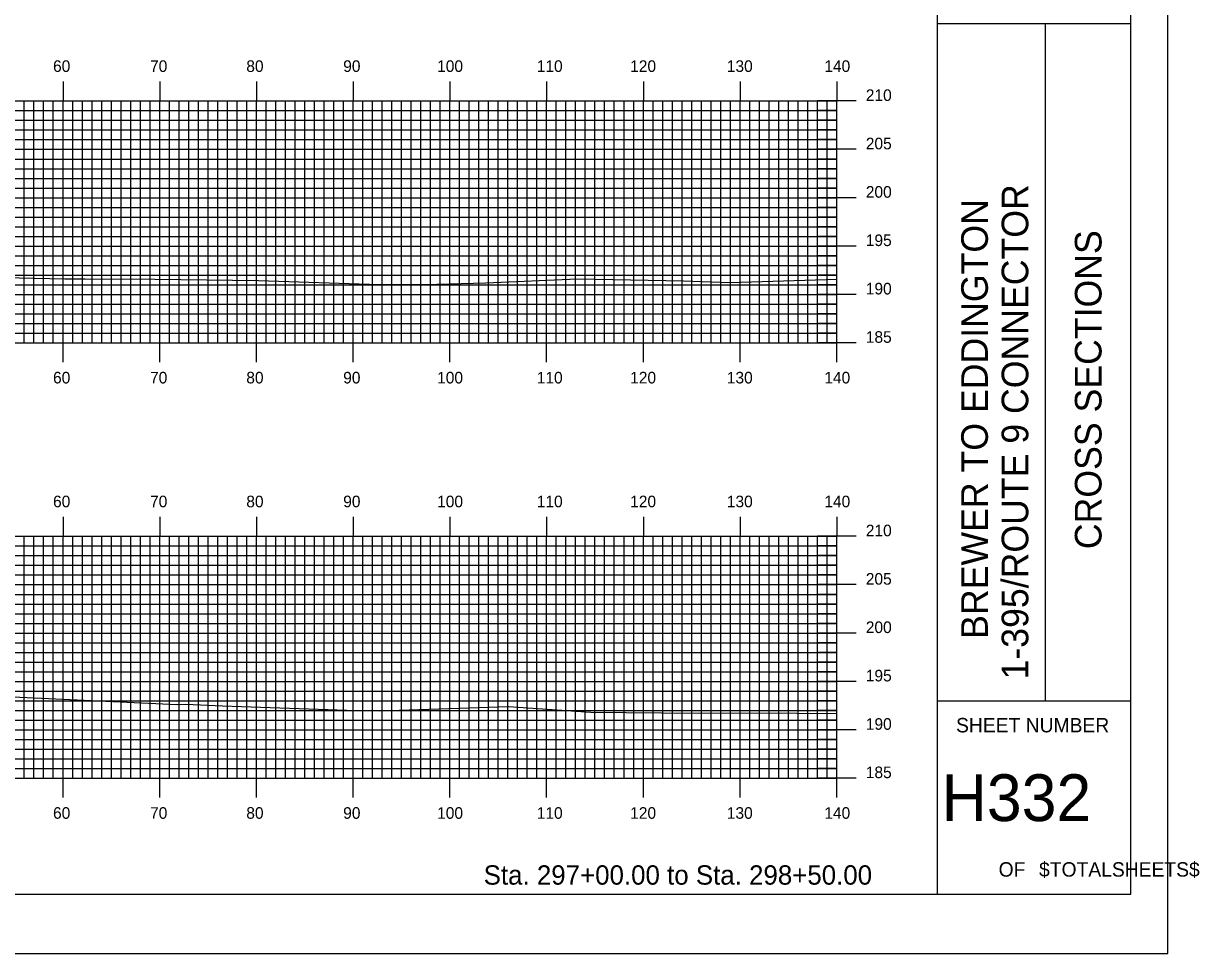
# Model space of a CAD drawing. Extents: x 1814915 to 1815259, y 442591 to 442811.
# Drawn here: x 1815136.9 to 1815258.5, y 442590.5 to 442686.7 of the extents above; entities that cross this region are included whole.
import ezdxf

# ---------------------------------------------------------------- set-up
doc = ezdxf.new("R2010")
doc.units = 0
for name, color, linetype in [('BORDER', 7, 'Continuous'), ('H_V ANNOTATION', 7, 'Continuous'), ('MAJOR', 7, 'Continuous'), ('MINOR', 7, 'Continuous'), ('PLOT BOUNDARY', 7, 'Continuous'), ('S_Roadway_Centerline', 7, 'Continuous')]:
    doc.layers.add(name, color=color, linetype=linetype)

msp = doc.modelspace()

# ---------------------------------------------------------------- linework, layer by layer
at = {"layer": 'BORDER'}
for p, q in [((1815231.42, 442596.67), (1815231.42, 442806.67)), ((1815231.42, 442686.67), (1815251.42, 442686.67)), ((1815242.6, 442616.67), (1815242.6, 442686.67)), ((1815231.42, 442616.67), (1815251.42, 442616.67))]:
    msp.add_line(p, q, dxfattribs=at)
msp.add_lwpolyline([(1814931.42, 442596.67), (1815251.42, 442596.67), (1815251.42, 442806.67), (1814931.42, 442806.67)], close=True, dxfattribs=at)
at = {"layer": 'MAJOR'}
for p, q in [((1815141.02, 442680.67), (1815141.02, 442678.67)), ((1815151.02, 442680.67), (1815151.02, 442678.67)), ((1815161.02, 442680.67), (1815161.02, 442678.67)), ((1815171.02, 442680.67), (1815171.02, 442678.67)), ((1815181.02, 442680.67), (1815181.02, 442678.67)), ((1815191.02, 442680.67), (1815191.02, 442678.67)), ((1815201.02, 442680.67), (1815201.02, 442678.67)), ((1815211.02, 442680.67), (1815211.02, 442678.67)), ((1815221.02, 442680.67), (1815221.02, 442678.67)), ((1814941.02, 442678.67), (1815221.02, 442678.67)), ((1814941.02, 442678.67), (1815221.02, 442678.67)), ((1815141.02, 442653.67), (1815141.02, 442678.67)), ((1815151.02, 442653.67), (1815151.02, 442678.67)), ((1815161.02, 442653.67), (1815161.02, 442678.67)), ((1815171.02, 442653.67), (1815171.02, 442678.67)), ((1815181.02, 442653.67), (1815181.02, 442678.67)), ((1815191.02, 442653.67), (1815191.02, 442678.67)), ((1815201.02, 442653.67), (1815201.02, 442678.67)), ((1815211.02, 442653.67), (1815211.02, 442678.67)), ((1815223.02, 442678.67), (1815219.02, 442678.67)), ((1815221.02, 442653.67), (1815221.02, 442678.67)), ((1815221.02, 442653.67), (1815221.02, 442678.67)), ((1814941.02, 442673.67), (1815221.02, 442673.67)), ((1815223.02, 442673.67), (1815219.02, 442673.67)), ((1814941.02, 442668.67), (1815221.02, 442668.67)), ((1815223.02, 442668.67), (1815219.02, 442668.67)), ((1814941.02, 442663.67), (1815221.02, 442663.67)), ((1815223.02, 442663.67), (1815219.02, 442663.67)), ((1814941.02, 442658.67), (1815221.02, 442658.67)), ((1815223.02, 442658.67), (1815219.02, 442658.67)), ((1814941.02, 442653.67), (1815221.02, 442653.67)), ((1814941.02, 442653.67), (1815221.02, 442653.67)), ((1815141.02, 442651.66), (1815141.02, 442653.67)), ((1815151.02, 442651.66), (1815151.02, 442653.67)), ((1815161.02, 442651.66), (1815161.02, 442653.67)), ((1815171.02, 442651.66), (1815171.02, 442653.67)), ((1815181.02, 442651.66), (1815181.02, 442653.67)), ((1815191.02, 442651.66), (1815191.02, 442653.67)), ((1815201.02, 442651.66), (1815201.02, 442653.67)), ((1815211.02, 442651.66), (1815211.02, 442653.67)), ((1815223.02, 442653.67), (1815219.02, 442653.67)), ((1815221.02, 442651.66), (1815221.02, 442653.67)), ((1815141.02, 442635.67), (1815141.02, 442633.67)), ((1815151.02, 442635.67), (1815151.02, 442633.67)), ((1815161.02, 442635.67), (1815161.02, 442633.67)), ((1815171.02, 442635.67), (1815171.02, 442633.67)), ((1815181.02, 442635.67), (1815181.02, 442633.67)), ((1815191.02, 442635.67), (1815191.02, 442633.67)), ((1815201.02, 442635.67), (1815201.02, 442633.67)), ((1815211.02, 442635.67), (1815211.02, 442633.67)), ((1815221.02, 442635.67), (1815221.02, 442633.67)), ((1814941.02, 442633.67), (1815221.02, 442633.67)), ((1814941.02, 442633.67), (1815221.02, 442633.67)), ((1815141.02, 442608.67), (1815141.02, 442633.67)), ((1815151.02, 442608.67), (1815151.02, 442633.67)), ((1815161.02, 442608.67), (1815161.02, 442633.67)), ((1815171.02, 442608.67), (1815171.02, 442633.67)), ((1815181.02, 442608.67), (1815181.02, 442633.67)), ((1815191.02, 442608.67), (1815191.02, 442633.67)), ((1815201.02, 442608.67), (1815201.02, 442633.67)), ((1815211.02, 442608.67), (1815211.02, 442633.67)), ((1815223.02, 442633.67), (1815219.02, 442633.67)), ((1815221.02, 442608.67), (1815221.02, 442633.67)), ((1815221.02, 442608.67), (1815221.02, 442633.67)), ((1814941.02, 442628.67), (1815221.02, 442628.67)), ((1815223.02, 442628.67), (1815219.02, 442628.67)), ((1814941.02, 442623.67), (1815221.02, 442623.67)), ((1815223.02, 442623.67), (1815219.02, 442623.67)), ((1814941.02, 442618.67), (1815221.02, 442618.67)), ((1815223.02, 442618.67), (1815219.02, 442618.67)), ((1814941.02, 442613.67), (1815221.02, 442613.67)), ((1815223.02, 442613.67), (1815219.02, 442613.67)), ((1814941.02, 442608.67), (1815221.02, 442608.67)), ((1814941.02, 442608.67), (1815221.02, 442608.67)), ((1815141.02, 442606.66), (1815141.02, 442608.67)), ((1815151.02, 442606.66), (1815151.02, 442608.67)), ((1815161.02, 442606.66), (1815161.02, 442608.67)), ((1815171.02, 442606.66), (1815171.02, 442608.67)), ((1815181.02, 442606.66), (1815181.02, 442608.67)), ((1815191.02, 442606.66), (1815191.02, 442608.67)), ((1815201.02, 442606.66), (1815201.02, 442608.67)), ((1815211.02, 442606.66), (1815211.02, 442608.67)), ((1815223.02, 442608.67), (1815219.02, 442608.67)), ((1815221.02, 442606.66), (1815221.02, 442608.67))]:
    msp.add_line(p, q, dxfattribs=at)
at = {"layer": 'MINOR'}
for p, q in [((1815137.02, 442653.67), (1815137.02, 442678.67)), ((1815138.02, 442653.67), (1815138.02, 442678.67)), ((1815139.02, 442653.67), (1815139.02, 442678.67)), ((1815140.02, 442653.67), (1815140.02, 442678.67)), ((1815142.02, 442653.67), (1815142.02, 442678.67)), ((1815143.02, 442653.67), (1815143.02, 442678.67)), ((1815144.02, 442653.67), (1815144.02, 442678.67)), ((1815145.02, 442653.67), (1815145.02, 442678.67)), ((1815146.02, 442653.67), (1815146.02, 442678.67)), ((1815147.02, 442653.67), (1815147.02, 442678.67)), ((1815148.02, 442653.67), (1815148.02, 442678.67)), ((1815149.02, 442653.67), (1815149.02, 442678.67)), ((1815150.02, 442653.67), (1815150.02, 442678.67)), ((1815152.02, 442653.67), (1815152.02, 442678.67)), ((1815153.02, 442653.67), (1815153.02, 442678.67)), ((1815154.02, 442653.67), (1815154.02, 442678.67)), ((1815155.02, 442653.67), (1815155.02, 442678.67)), ((1815156.02, 442653.67), (1815156.02, 442678.67)), ((1815157.02, 442653.67), (1815157.02, 442678.67)), ((1815158.02, 442653.67), (1815158.02, 442678.67)), ((1815159.02, 442653.67), (1815159.02, 442678.67)), ((1815160.02, 442653.67), (1815160.02, 442678.67)), ((1815162.02, 442653.67), (1815162.02, 442678.67)), ((1815163.02, 442653.67), (1815163.02, 442678.67)), ((1815164.02, 442653.67), (1815164.02, 442678.67)), ((1815165.02, 442653.67), (1815165.02, 442678.67)), ((1815166.02, 442653.67), (1815166.02, 442678.67)), ((1815167.02, 442653.67), (1815167.02, 442678.67)), ((1815168.02, 442653.67), (1815168.02, 442678.67)), ((1815169.02, 442653.67), (1815169.02, 442678.67)), ((1815170.02, 442653.67), (1815170.02, 442678.67)), ((1815172.02, 442653.67), (1815172.02, 442678.67)), ((1815173.02, 442653.67), (1815173.02, 442678.67)), ((1815174.02, 442653.67), (1815174.02, 442678.67)), ((1815175.02, 442653.67), (1815175.02, 442678.67)), ((1815176.02, 442653.67), (1815176.02, 442678.67)), ((1815177.02, 442653.67), (1815177.02, 442678.67)), ((1815178.02, 442653.67), (1815178.02, 442678.67)), ((1815179.02, 442653.67), (1815179.02, 442678.67)), ((1815180.02, 442653.67), (1815180.02, 442678.67)), ((1815182.02, 442653.67), (1815182.02, 442678.67)), ((1815183.02, 442653.67), (1815183.02, 442678.67)), ((1815184.02, 442653.67), (1815184.02, 442678.67)), ((1815185.02, 442653.67), (1815185.02, 442678.67)), ((1815186.02, 442653.67), (1815186.02, 442678.67)), ((1815187.02, 442653.67), (1815187.02, 442678.67)), ((1815188.02, 442653.67), (1815188.02, 442678.67)), ((1815189.02, 442653.67), (1815189.02, 442678.67)), ((1815190.02, 442653.67), (1815190.02, 442678.67)), ((1815192.02, 442653.67), (1815192.02, 442678.67)), ((1815193.02, 442653.67), (1815193.02, 442678.67)), ((1815194.02, 442653.67), (1815194.02, 442678.67)), ((1815195.02, 442653.67), (1815195.02, 442678.67)), ((1815196.02, 442653.67), (1815196.02, 442678.67)), ((1815197.02, 442653.67), (1815197.02, 442678.67)), ((1815198.02, 442653.67), (1815198.02, 442678.67)), ((1815199.02, 442653.67), (1815199.02, 442678.67)), ((1815200.02, 442653.67), (1815200.02, 442678.67)), ((1815202.02, 442653.67), (1815202.02, 442678.67)), ((1815203.02, 442653.67), (1815203.02, 442678.67)), ((1815204.02, 442653.67), (1815204.02, 442678.67)), ((1815205.02, 442653.67), (1815205.02, 442678.67)), ((1815206.02, 442653.67), (1815206.02, 442678.67)), ((1815207.02, 442653.67), (1815207.02, 442678.67)), ((1815208.02, 442653.67), (1815208.02, 442678.67)), ((1815209.02, 442653.67), (1815209.02, 442678.67)), ((1815210.02, 442653.67), (1815210.02, 442678.67)), ((1815212.02, 442653.67), (1815212.02, 442678.67)), ((1815213.02, 442653.67), (1815213.02, 442678.67)), ((1815214.02, 442653.67), (1815214.02, 442678.67)), ((1815215.02, 442653.67), (1815215.02, 442678.67)), ((1815216.02, 442653.67), (1815216.02, 442678.67)), ((1815217.02, 442653.67), (1815217.02, 442678.67)), ((1815218.02, 442653.67), (1815218.02, 442678.67)), ((1815219.02, 442653.67), (1815219.02, 442678.67)), ((1815220.02, 442653.67), (1815220.02, 442678.67)), ((1814941.02, 442677.67), (1815221.02, 442677.67)), ((1814941.02, 442676.67), (1815221.02, 442676.67)), ((1815221.02, 442677.67), (1815219.02, 442677.67)), ((1815221.02, 442676.67), (1815219.02, 442676.67)), ((1814941.02, 442675.67), (1815221.02, 442675.67)), ((1815221.02, 442675.67), (1815219.02, 442675.67)), ((1814941.02, 442674.67), (1815221.02, 442674.67)), ((1815221.02, 442674.67), (1815219.02, 442674.67)), ((1814941.02, 442672.67), (1815221.02, 442672.67)), ((1814941.02, 442671.67), (1815221.02, 442671.67)), ((1815221.02, 442672.67), (1815219.02, 442672.67)), ((1815221.02, 442671.67), (1815219.02, 442671.67)), ((1814941.02, 442670.67), (1815221.02, 442670.67)), ((1815221.02, 442670.67), (1815219.02, 442670.67)), ((1814941.02, 442669.67), (1815221.02, 442669.67)), ((1815221.02, 442669.67), (1815219.02, 442669.67)), ((1814941.02, 442667.67), (1815221.02, 442667.67)), ((1815221.02, 442667.67), (1815219.02, 442667.67)), ((1814941.02, 442666.67), (1815221.02, 442666.67)), ((1814941.02, 442665.67), (1815221.02, 442665.67)), ((1815221.02, 442666.67), (1815219.02, 442666.67)), ((1815221.02, 442665.67), (1815219.02, 442665.67)), ((1814941.02, 442664.67), (1815221.02, 442664.67)), ((1815221.02, 442664.67), (1815219.02, 442664.67)), ((1814941.02, 442662.67), (1815221.02, 442662.67)), ((1815221.02, 442662.67), (1815219.02, 442662.67)), ((1814941.02, 442661.67), (1815221.02, 442661.67)), ((1815221.02, 442661.67), (1815219.02, 442661.67)), ((1814941.02, 442660.67), (1815221.02, 442660.67)), ((1814941.02, 442659.67), (1815221.02, 442659.67)), ((1815221.02, 442660.67), (1815219.02, 442660.67)), ((1815221.02, 442659.67), (1815219.02, 442659.67)), ((1814941.02, 442657.67), (1815221.02, 442657.67)), ((1815221.02, 442657.67), (1815219.02, 442657.67)), ((1814941.02, 442656.67), (1815221.02, 442656.67)), ((1815221.02, 442656.67), (1815219.02, 442656.67)), ((1814941.02, 442655.67), (1815221.02, 442655.67)), ((1814941.02, 442654.67), (1815221.02, 442654.67)), ((1815221.02, 442655.67), (1815219.02, 442655.67)), ((1815221.02, 442654.67), (1815219.02, 442654.67)), ((1815137.02, 442608.67), (1815137.02, 442633.67)), ((1815138.02, 442608.67), (1815138.02, 442633.67)), ((1815139.02, 442608.67), (1815139.02, 442633.67)), ((1815140.02, 442608.67), (1815140.02, 442633.67)), ((1815142.02, 442608.67), (1815142.02, 442633.67)), ((1815143.02, 442608.67), (1815143.02, 442633.67)), ((1815144.02, 442608.67), (1815144.02, 442633.67)), ((1815145.02, 442608.67), (1815145.02, 442633.67)), ((1815146.02, 442608.67), (1815146.02, 442633.67)), ((1815147.02, 442608.67), (1815147.02, 442633.67)), ((1815148.02, 442608.67), (1815148.02, 442633.67)), ((1815149.02, 442608.67), (1815149.02, 442633.67)), ((1815150.02, 442608.67), (1815150.02, 442633.67)), ((1815152.02, 442608.67), (1815152.02, 442633.67)), ((1815153.02, 442608.67), (1815153.02, 442633.67)), ((1815154.02, 442608.67), (1815154.02, 442633.67)), ((1815155.02, 442608.67), (1815155.02, 442633.67)), ((1815156.02, 442608.67), (1815156.02, 442633.67)), ((1815157.02, 442608.67), (1815157.02, 442633.67)), ((1815158.02, 442608.67), (1815158.02, 442633.67)), ((1815159.02, 442608.67), (1815159.02, 442633.67)), ((1815160.02, 442608.67), (1815160.02, 442633.67)), ((1815162.02, 442608.67), (1815162.02, 442633.67)), ((1815163.02, 442608.67), (1815163.02, 442633.67)), ((1815164.02, 442608.67), (1815164.02, 442633.67)), ((1815165.02, 442608.67), (1815165.02, 442633.67)), ((1815166.02, 442608.67), (1815166.02, 442633.67)), ((1815167.02, 442608.67), (1815167.02, 442633.67)), ((1815168.02, 442608.67), (1815168.02, 442633.67)), ((1815169.02, 442608.67), (1815169.02, 442633.67)), ((1815170.02, 442608.67), (1815170.02, 442633.67)), ((1815172.02, 442608.67), (1815172.02, 442633.67)), ((1815173.02, 442608.67), (1815173.02, 442633.67)), ((1815174.02, 442608.67), (1815174.02, 442633.67)), ((1815175.02, 442608.67), (1815175.02, 442633.67)), ((1815176.02, 442608.67), (1815176.02, 442633.67)), ((1815177.02, 442608.67), (1815177.02, 442633.67)), ((1815178.02, 442608.67), (1815178.02, 442633.67)), ((1815179.02, 442608.67), (1815179.02, 442633.67)), ((1815180.02, 442608.67), (1815180.02, 442633.67)), ((1815182.02, 442608.67), (1815182.02, 442633.67)), ((1815183.02, 442608.67), (1815183.02, 442633.67)), ((1815184.02, 442608.67), (1815184.02, 442633.67)), ((1815185.02, 442608.67), (1815185.02, 442633.67)), ((1815186.02, 442608.67), (1815186.02, 442633.67)), ((1815187.02, 442608.67), (1815187.02, 442633.67)), ((1815188.02, 442608.67), (1815188.02, 442633.67)), ((1815189.02, 442608.67), (1815189.02, 442633.67)), ((1815190.02, 442608.67), (1815190.02, 442633.67)), ((1815192.02, 442608.67), (1815192.02, 442633.67)), ((1815193.02, 442608.67), (1815193.02, 442633.67)), ((1815194.02, 442608.67), (1815194.02, 442633.67)), ((1815195.02, 442608.67), (1815195.02, 442633.67)), ((1815196.02, 442608.67), (1815196.02, 442633.67)), ((1815197.02, 442608.67), (1815197.02, 442633.67)), ((1815198.02, 442608.67), (1815198.02, 442633.67)), ((1815199.02, 442608.67), (1815199.02, 442633.67)), ((1815200.02, 442608.67), (1815200.02, 442633.67)), ((1815202.02, 442608.67), (1815202.02, 442633.67)), ((1815203.02, 442608.67), (1815203.02, 442633.67)), ((1815204.02, 442608.67), (1815204.02, 442633.67)), ((1815205.02, 442608.67), (1815205.02, 442633.67)), ((1815206.02, 442608.67), (1815206.02, 442633.67)), ((1815207.02, 442608.67), (1815207.02, 442633.67)), ((1815208.02, 442608.67), (1815208.02, 442633.67)), ((1815209.02, 442608.67), (1815209.02, 442633.67)), ((1815210.02, 442608.67), (1815210.02, 442633.67)), ((1815212.02, 442608.67), (1815212.02, 442633.67)), ((1815213.02, 442608.67), (1815213.02, 442633.67)), ((1815214.02, 442608.67), (1815214.02, 442633.67)), ((1815215.02, 442608.67), (1815215.02, 442633.67)), ((1815216.02, 442608.67), (1815216.02, 442633.67)), ((1815217.02, 442608.67), (1815217.02, 442633.67)), ((1815218.02, 442608.67), (1815218.02, 442633.67)), ((1815219.02, 442608.67), (1815219.02, 442633.67)), ((1815220.02, 442608.67), (1815220.02, 442633.67)), ((1814941.02, 442632.67), (1815221.02, 442632.67)), ((1814941.02, 442631.67), (1815221.02, 442631.67)), ((1815221.02, 442632.67), (1815219.02, 442632.67)), ((1815221.02, 442631.67), (1815219.02, 442631.67)), ((1814941.02, 442630.67), (1815221.02, 442630.67)), ((1815221.02, 442630.67), (1815219.02, 442630.67)), ((1814941.02, 442629.67), (1815221.02, 442629.67)), ((1815221.02, 442629.67), (1815219.02, 442629.67)), ((1814941.02, 442627.67), (1815221.02, 442627.67)), ((1814941.02, 442626.67), (1815221.02, 442626.67)), ((1815221.02, 442627.67), (1815219.02, 442627.67)), ((1815221.02, 442626.67), (1815219.02, 442626.67)), ((1814941.02, 442625.67), (1815221.02, 442625.67)), ((1815221.02, 442625.67), (1815219.02, 442625.67)), ((1814941.02, 442624.67), (1815221.02, 442624.67)), ((1815221.02, 442624.67), (1815219.02, 442624.67)), ((1814941.02, 442622.67), (1815221.02, 442622.67)), ((1815221.02, 442622.67), (1815219.02, 442622.67)), ((1814941.02, 442621.67), (1815221.02, 442621.67)), ((1814941.02, 442620.67), (1815221.02, 442620.67)), ((1815221.02, 442621.67), (1815219.02, 442621.67)), ((1815221.02, 442620.67), (1815219.02, 442620.67)), ((1814941.02, 442619.67), (1815221.02, 442619.67)), ((1815221.02, 442619.67), (1815219.02, 442619.67)), ((1814941.02, 442617.67), (1815221.02, 442617.67)), ((1815221.02, 442617.67), (1815219.02, 442617.67)), ((1814941.02, 442616.67), (1815221.02, 442616.67)), ((1815221.02, 442616.67), (1815219.02, 442616.67)), ((1814941.02, 442615.67), (1815221.02, 442615.67)), ((1814941.02, 442614.67), (1815221.02, 442614.67)), ((1815221.02, 442615.67), (1815219.02, 442615.67)), ((1815221.02, 442614.67), (1815219.02, 442614.67)), ((1814941.02, 442612.67), (1815221.02, 442612.67)), ((1815221.02, 442612.67), (1815219.02, 442612.67)), ((1814941.02, 442611.67), (1815221.02, 442611.67)), ((1815221.02, 442611.67), (1815219.02, 442611.67)), ((1814941.02, 442610.67), (1815221.02, 442610.67)), ((1814941.02, 442609.67), (1815221.02, 442609.67)), ((1815221.02, 442610.67), (1815219.02, 442610.67)), ((1815221.02, 442609.67), (1815219.02, 442609.67))]:
    msp.add_line(p, q, dxfattribs=at)
at = {"layer": 'PLOT BOUNDARY'}
msp.add_lwpolyline([(1814915.23, 442590.55), (1815255.23, 442590.55), (1815255.23, 442810.55), (1814915.23, 442810.55)], close=True, dxfattribs=at)
at = {"layer": 'S_Roadway_Centerline'}
for points in [[(1815117.76, 442660.81), (1815141.21, 442660.3), (1815143.32, 442660.3), (1815150.51, 442660.24), (1815161.23, 442660.12), (1815173.74, 442659.7), (1815178.38, 442659.71), (1815184.74, 442659.87), (1815194.2, 442660.29), (1815205.17, 442660.07), (1815210.01, 442659.91), (1815221.02, 442660.26)], [(1815135.82, 442617.07), (1815152.82, 442616.3), (1815153.72, 442616.32), (1815157.51, 442616.16), (1815170.37, 442615.69), (1815173.7, 442615.63), (1815187.07, 442616.06), (1815195.59, 442615.5), (1815202.9, 442615.43), (1815216.88, 442615.37), (1815221.02, 442615.35)]]:
    msp.add_lwpolyline(points, dxfattribs=at)

# ---------------------------------------------------------------- texts
at = {"layer": 'BORDER'}
for s, p in [('1-395/ROUTE 9 CONNECTOR', (1815240.82, 442618.87)), ('BREWER TO EDDINGTON', (1815236.64, 442623.07)), ('CROSS SECTIONS', (1815248.39, 442632.34))]:
    msp.add_text(s, height=2.7557, rotation=90, dxfattribs=at).set_placement(p)
for s, height, p in [('SHEET NUMBER', 1.4905, (1815233.35, 442613.4)), ('H332', 4.839, (1815231.86, 442604.23)), ('OF', 1.491, (1815237.75, 442598.49)), ('$TOTALSHEETS$', 1.4905, (1815241.93, 442598.49))]:
    msp.add_text(s, height=height, dxfattribs=at).set_placement(p)
at = {"layer": 'H_V ANNOTATION'}
for s, height, p in [('60', 1.2, (1815139.99, 442681.67)), ('70', 1.2, (1815150.02, 442681.67)), ('80', 1.2, (1815159.97, 442681.67)), ('90', 1.2, (1815169.99, 442681.67)), ('100', 1.2, (1815179.7, 442681.67)), ('110', 1.2, (1815190, 442681.67)), ('120', 1.2, (1815199.66, 442681.67)), ('130', 1.2, (1815209.65, 442681.67)), ('140', 1.2, (1815219.73, 442681.67)), ('210', 1.2, (1815224.02, 442678.67)), ('205', 1.2, (1815224.02, 442673.67)), ('200', 1.2, (1815224.02, 442668.67)), ('195', 1.2, (1815224.02, 442663.67)), ('190', 1.2, (1815224.02, 442658.67)), ('185', 1.2, (1815224.02, 442653.67)), ('60', 1.2, (1815139.99, 442649.47)), ('70', 1.2, (1815150.02, 442649.47)), ('80', 1.2, (1815159.97, 442649.47)), ('90', 1.2, (1815169.99, 442649.47)), ('100', 1.2, (1815179.7, 442649.47)), ('110', 1.2, (1815190, 442649.47)), ('120', 1.2, (1815199.66, 442649.47)), ('130', 1.2, (1815209.65, 442649.47)), ('140', 1.2, (1815219.73, 442649.47)), ('60', 1.2, (1815139.99, 442636.67)), ('70', 1.2, (1815150.02, 442636.67)), ('80', 1.2, (1815159.97, 442636.67)), ('90', 1.2, (1815169.99, 442636.67)), ('100', 1.2, (1815179.7, 442636.67)), ('110', 1.2, (1815190, 442636.67)), ('120', 1.2, (1815199.66, 442636.67)), ('130', 1.2, (1815209.65, 442636.67)), ('140', 1.2, (1815219.73, 442636.67)), ('210', 1.2, (1815224.02, 442633.67)), ('205', 1.2, (1815224.02, 442628.67)), ('200', 1.2, (1815224.02, 442623.67)), ('195', 1.2, (1815224.02, 442618.67)), ('190', 1.2, (1815224.02, 442613.67)), ('185', 1.2, (1815224.02, 442608.67)), ('60', 1.2, (1815139.99, 442604.47)), ('70', 1.2, (1815150.02, 442604.47)), ('80', 1.2, (1815159.97, 442604.47)), ('90', 1.2, (1815169.99, 442604.47)), ('100', 1.2, (1815179.7, 442604.47)), ('110', 1.2, (1815190, 442604.47)), ('120', 1.2, (1815199.66, 442604.47)), ('130', 1.2, (1815209.65, 442604.47)), ('140', 1.2, (1815219.73, 442604.47)), ('Sta. 297+00.00 to Sta. 298+50.00', 2.0004, (1815184.51, 442597.66))]:
    msp.add_text(s, height=height, dxfattribs=at).set_placement(p)

doc.saveas('drawing.dxf')
